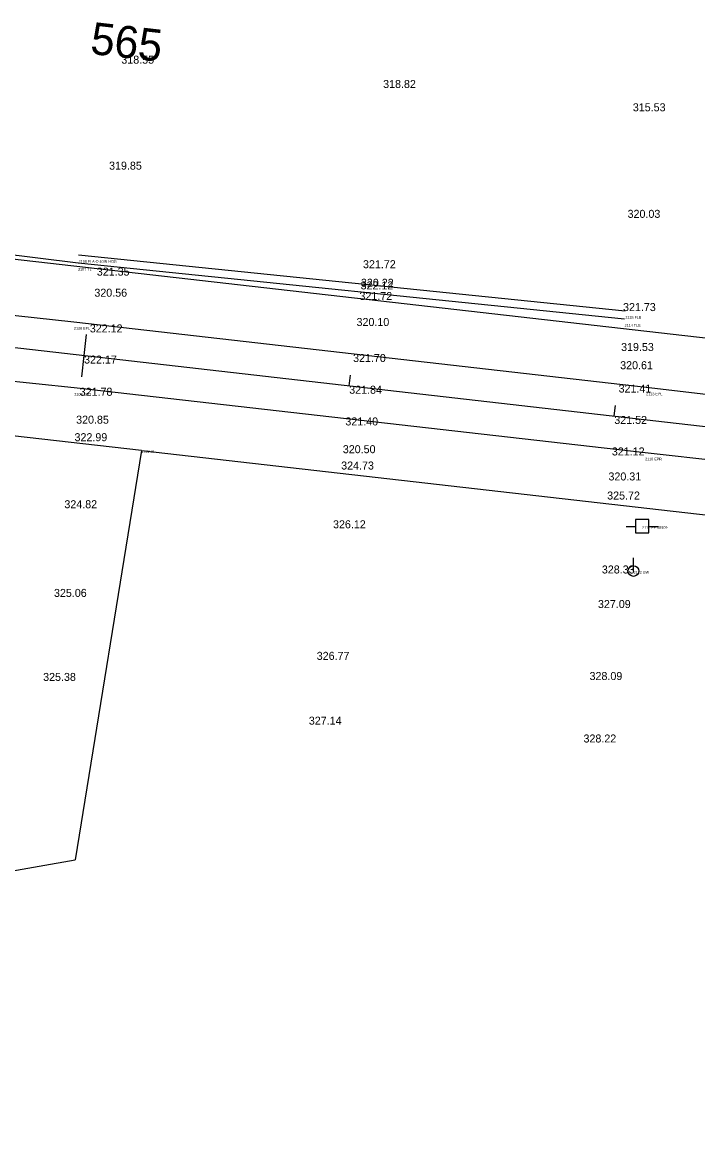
# Model space of a CAD drawing. Extents: x 49683 to 58852, y 49525 to 54803.
# Drawn here: x 57269.8 to 57523, y 53727.3 to 54146.3 of the extents above; entities that cross this region are included whole.
import ezdxf

# ---------------------------------------------------------------- set-up
doc = ezdxf.new("R2010")
doc.units = 0
for name, color, linetype in [('Level 1', 7, 'Continuous'), ('Level 11', 7, 'Continuous'), ('Level 12', 7, 'Continuous'), ('Level 13', 7, 'Continuous'), ('Level 21', 7, 'Continuous'), ('Level 3', 7, 'Continuous'), ('Level 32', 7, 'Continuous'), ('Level 53', 7, 'Continuous'), ('Level 58', 7, 'Continuous'), ('Level 59', 7, 'Continuous'), ('Level 61', 7, 'Continuous'), ('Level 62', 7, 'Continuous'), ('Level 8', 7, 'Continuous'), ('Level 9', 7, 'Continuous')]:
    doc.layers.add(name, color=color, linetype=linetype)

# ---------------------------------------------------------------- blocks, each defined once
blk = doc.blocks.new('PP')
at = {"layer": 'Level 9'}
for p, q in [((2.53, 2.45), (-2.47, 2.45)), ((-2.47, 2.45), (-2.47, -2.55)), ((2.53, -2.55), (2.53, 2.45)), ((-5.91, -0.11), (-2.44, -0.11)), ((-2.47, -2.55), (2.53, -2.55)), ((2.45, -0.11), (6.09, -0.11))]:
    blk.add_line(p, q, dxfattribs=at)
blk = doc.blocks.new('GW')
at = {"layer": 'Level 9'}
blk.add_line((0, 0), (0, 5), dxfattribs=at)
blk.add_circle((0, 0), 2, dxfattribs=at)

msp = doc.modelspace()

# ---------------------------------------------------------------- linework, layer by layer
at = {"layer": 'Level 1'}
for p, q in [((56981.58, 54056.82), (58783.3, 53851.37)), ((57292.96, 54021.32), (57293.87, 54029.26)), ((57292.06, 54013.37), (57292.96, 54021.32)), ((57392.32, 54009.99), (57392.77, 54013.96)), ((57491.68, 53998.66), (57492.13, 54002.63))]:
    msp.add_line(p, q, dxfattribs=at)
at = {"layer": 'Level 11'}
for p, q in [((57155.88, 54072.62), (57290.67, 54056.11)), ((57290.67, 54056.11), (57495.57, 54035.12))]:
    msp.add_line(p, q, dxfattribs=at)
at = {"layer": 'Level 12'}
for p in [(57314.41, 53985.66), (56690.99, 53727.29)]:
    msp.add_line(p, (57289.55, 53832.27), dxfattribs=at)
at = {"layer": 'Level 13'}
for p, q in [((57134.79, 54072.57), (58787.04, 53884.15)), ((57314.41, 53985.66), (56917.82, 54030.88)), ((57314.41, 53985.66), (58779.57, 53818.58))]:
    msp.add_line(p, q, dxfattribs=at)
at = {"layer": 'Level 3'}
for p, q in [((57169.61, 54047.04), (57289.1, 54034.02)), ((57289.1, 54034.02), (57503.69, 54009.45)), ((57167.04, 54022.13), (57289.26, 54009.3)), ((57289.26, 54009.3), (57503.24, 53984.99)), ((57503.69, 54009.45), (57780.7, 53977.52)), ((57503.24, 53984.99), (57776.18, 53954.21))]:
    msp.add_line(p, q, dxfattribs=at)
at = {"layer": 'Level 8'}
msp.add_line((57290.87, 54059.1), (57495.84, 54038.11), dxfattribs=at)

# ---------------------------------------------------------------- block references
at = {"layer": 'Level 9'}
for name, p in [('PP', (57502.09, 53957.35)), ('GW', (57498.91, 53940.5))]:
    msp.add_blockref(name, p, dxfattribs=at)

# ---------------------------------------------------------------- texts
at = {"layer": 'Level 21'}
msp.add_text('565', height=12, rotation=353.4944, dxfattribs=at).set_placement((57294.95, 54134.49))
at = {"layer": 'Level 32'}
for s, p in [('318.55', (57306.89, 54130.76)), ('318.82', (57405.04, 54121.65)), ('315.53', (57498.65, 54112.91)), ('319.85', (57302.29, 54091.03)), ('320.03', (57496.69, 54072.96)), ('321.72', (57397.49, 54054.07)), ('321.35', (57297.69, 54051.29)), ('322.12', (57396.6, 54046.12)), ('320.22', (57396.71, 54047.11)), ('320.56', (57296.78, 54043.38)), ('321.72', (57396.16, 54042.14)), ('321.73', (57494.98, 54038)), ('320.10', (57395.07, 54032.4)), ('322.12', (57295.07, 54030)), ('319.53', (57494.25, 54023.02)), ('322.17', (57292.92, 54018.32)), ('321.70', (57393.77, 54018.9)), ('320.61', (57493.91, 54016.19)), ('321.84', (57392.32, 54006.99)), ('321.41', (57493.32, 54007.44)), ('321.78', (57291.28, 54006.24)), ('320.85', (57289.94, 53995.77)), ('321.40', (57390.88, 53995.11)), ('321.52', (57491.7, 53995.67)), ('322.99', (57289.34, 53989.2)), ('320.50', (57389.92, 53984.7)), ('321.12', (57490.79, 53983.86)), ('324.73', (57389.31, 53978.58)), ('320.31', (57489.52, 53974.49)), ('325.72', (57489.04, 53967.33)), ('324.82', (57285.54, 53964.07)), ('326.12', (57386.25, 53956.55)), ('328.33', (57487.04, 53939.6)), ('325.06', (57281.63, 53930.81)), ('327.09', (57485.58, 53926.64)), ('326.77', (57380.14, 53907.21)), ('325.38', (57277.57, 53899.31)), ('328.09', (57482.43, 53899.64)), ('327.14', (57377.18, 53882.91)), ('328.22', (57480.16, 53876.22))]:
    msp.add_text(s, height=3, dxfattribs=at).set_placement(p)
at = {"layer": 'Level 53'}
for s, p in [('2106 EPL ', (57289.1, 54031.02)), ('2109 EPR ', (57289.26, 54006.3)), ('2113 EPL ', (57503.69, 54006.45)), ('2110 EPR ', (57503.24, 53981.99))]:
    msp.add_text(s, height=1, dxfattribs=at).set_placement(p)
at = {"layer": 'Level 58'}
for s, p in [('2108 FLA O 40IN HOG ', (57290.87, 54056.1)), ('2115 FLB ', (57495.84, 54035.11))]:
    msp.add_text(s, height=1, dxfattribs=at).set_placement(p)
at = {"layer": 'Level 59'}
for s, p in [('2111 PP 08909 ', (57502.09, 53956.35)), ('2112 GW ', (57498.91, 53939.5))]:
    msp.add_text(s, height=1, dxfattribs=at).set_placement(p)
at = {"layer": 'Level 61'}
for s, p in [('2107 TL ', (57290.67, 54053.11)), ('2114 TLB ', (57495.57, 54032.12))]:
    msp.add_text(s, height=1, dxfattribs=at).set_placement(p)
at = {"layer": 'Level 62'}
msp.add_text('1722 IP ', height=1, dxfattribs=at).set_placement((57314.44, 53984.83))

doc.saveas('drawing.dxf')
